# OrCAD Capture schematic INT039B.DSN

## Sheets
1 PAGE3 - CONFIG: size B; title: TUSB522PEVM INT039 Rev B: CONFIG; rev: B; note: 6590969
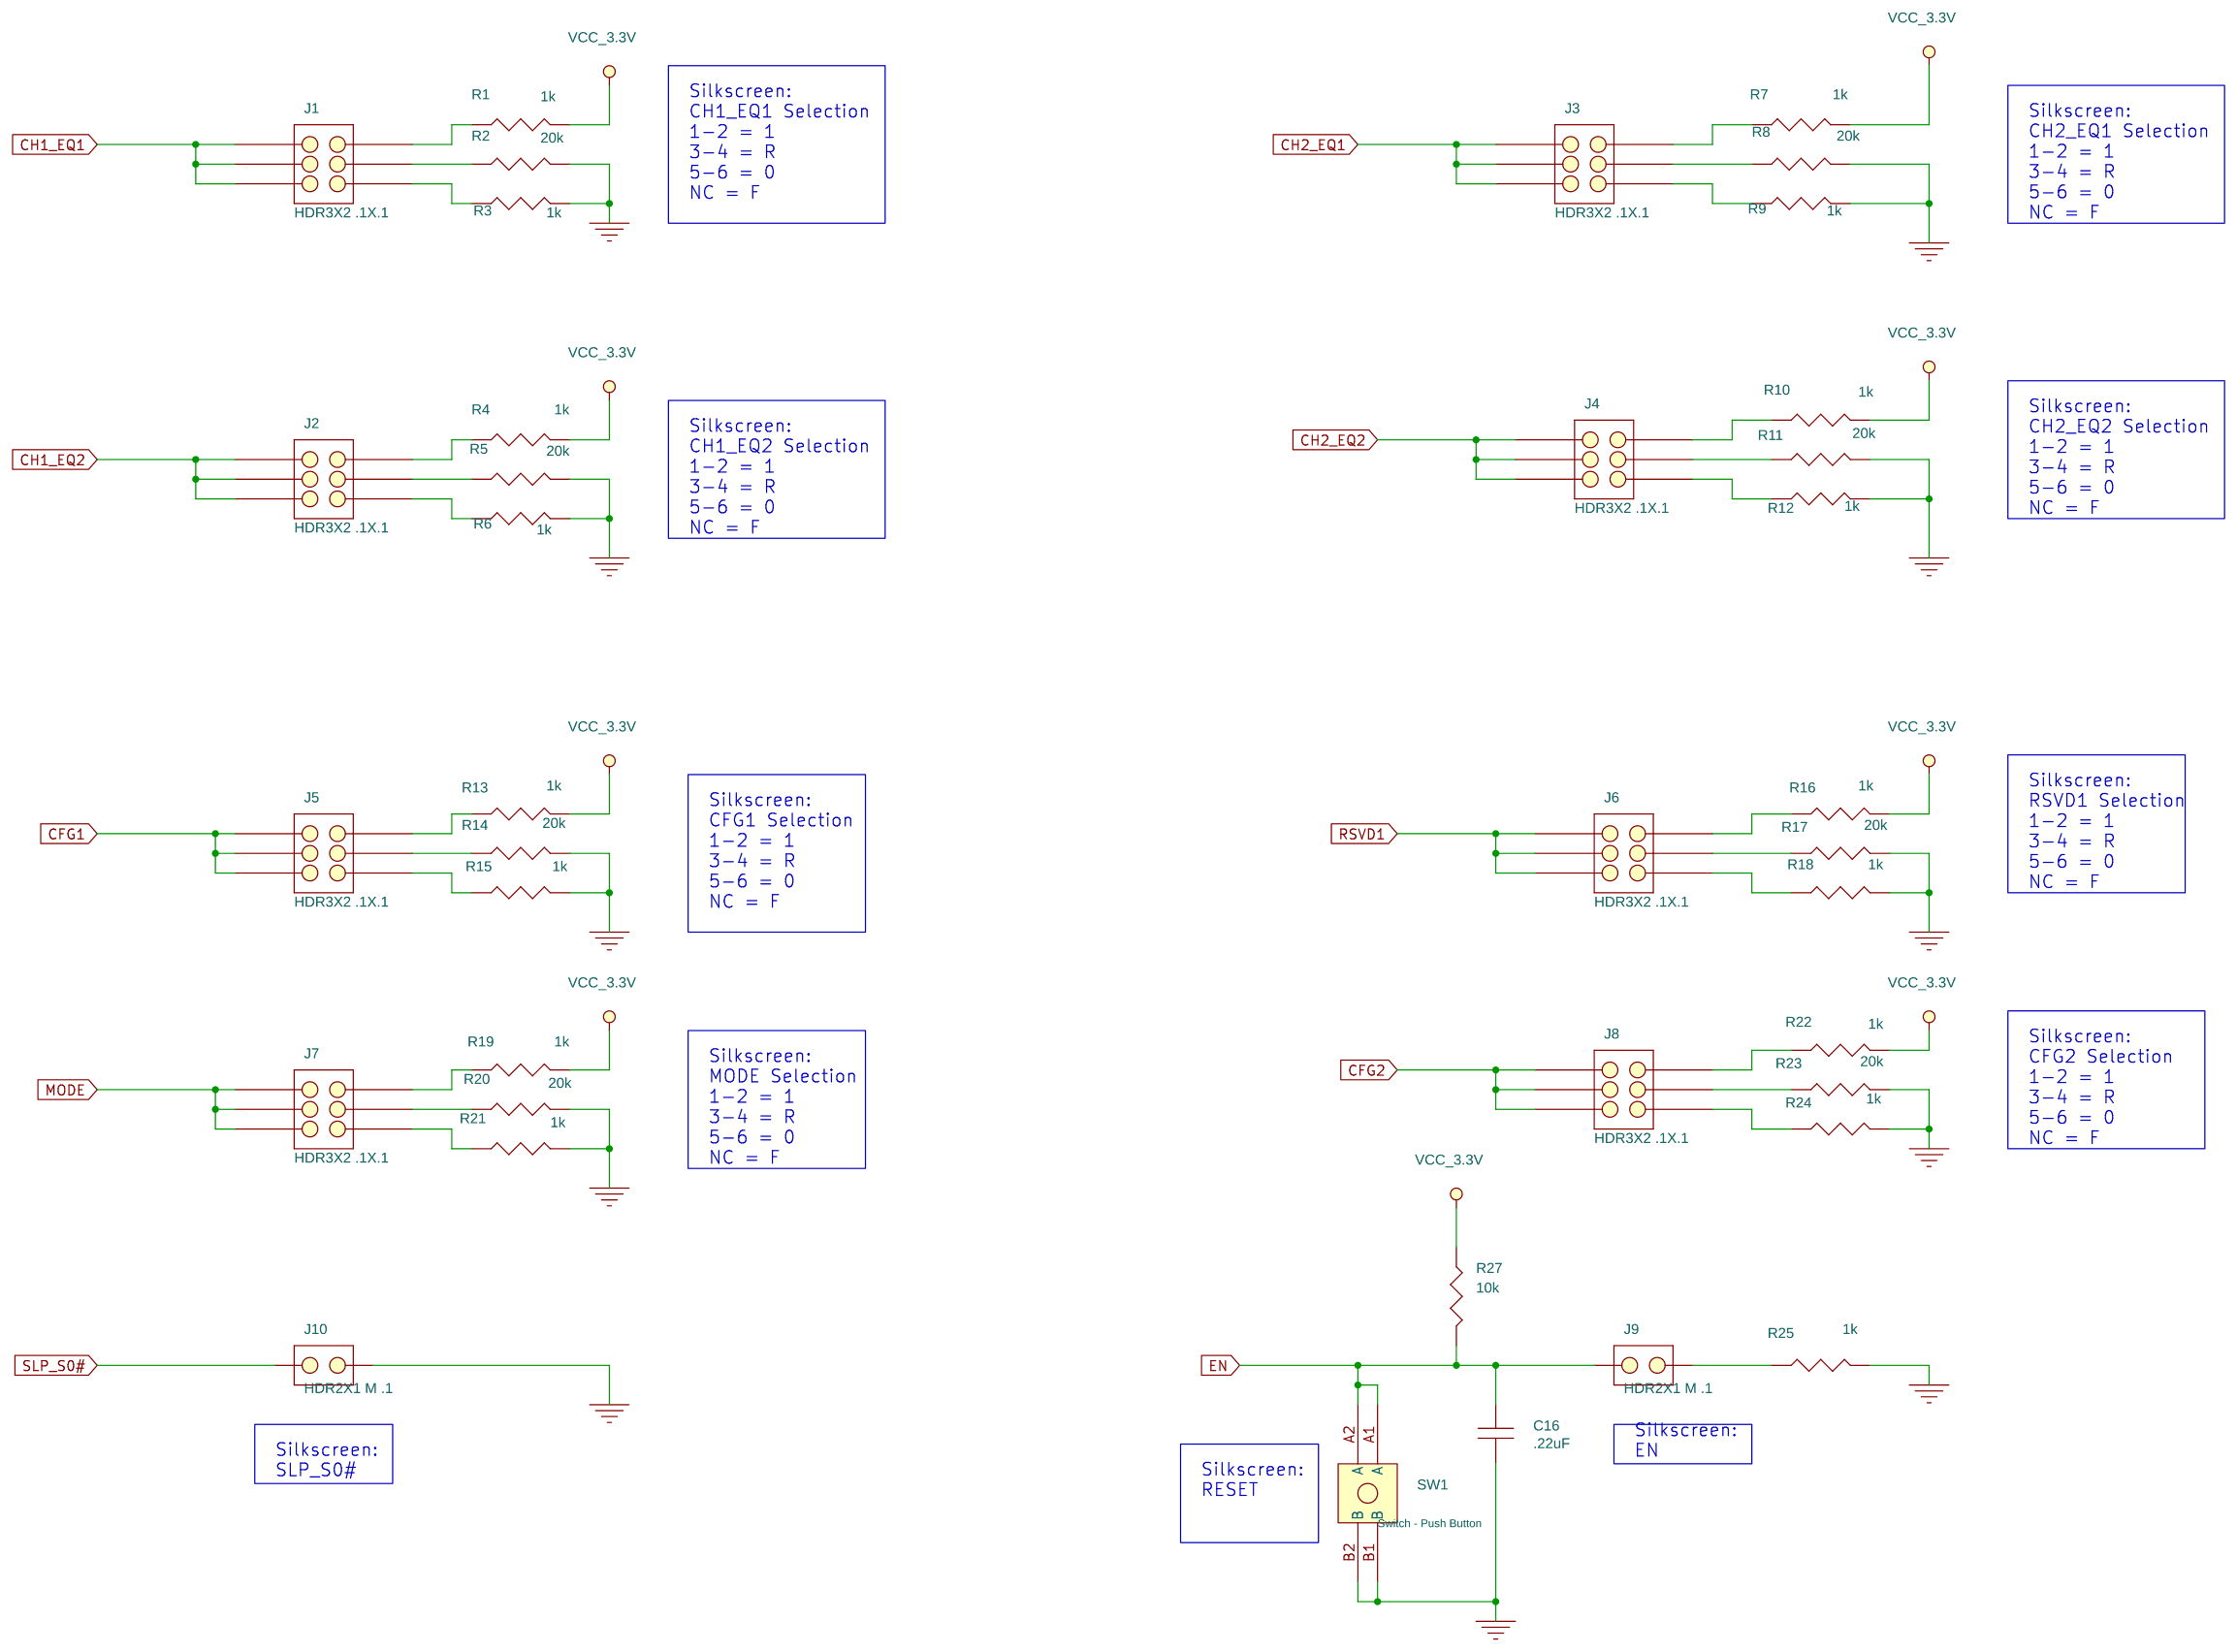
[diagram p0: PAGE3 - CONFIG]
2 PAGE1 - Block: title: TUSB522PEVM INT039 Rev B: Block
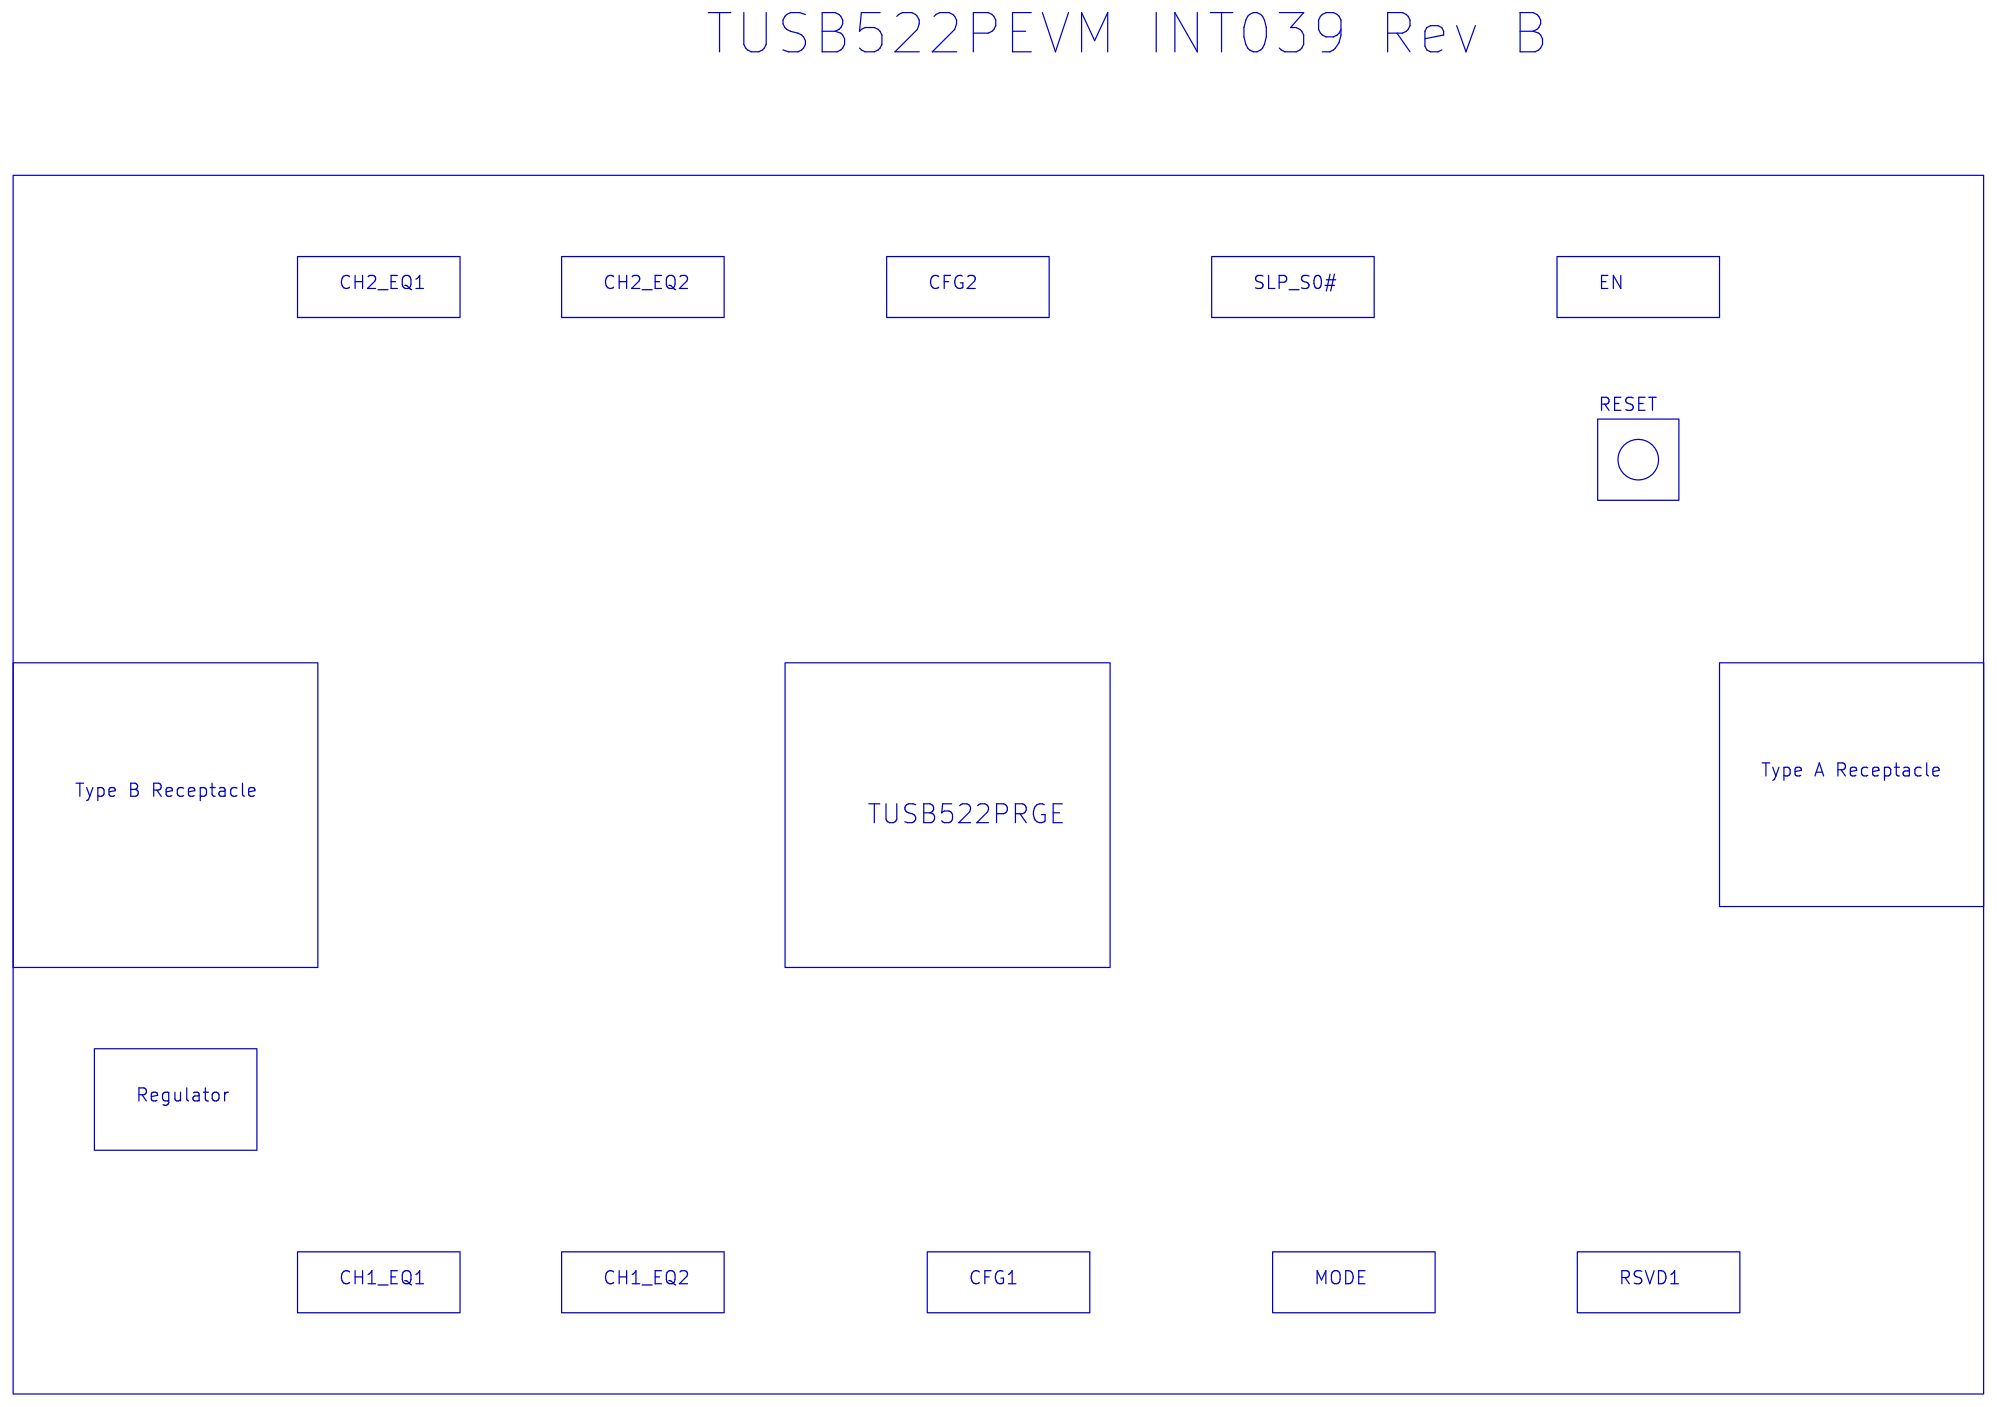
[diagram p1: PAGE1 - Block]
3 PAGE2 - HighSpeed/Power: size B; title: TUSB522PEVM INT039 Rev B: High-Speed/Power
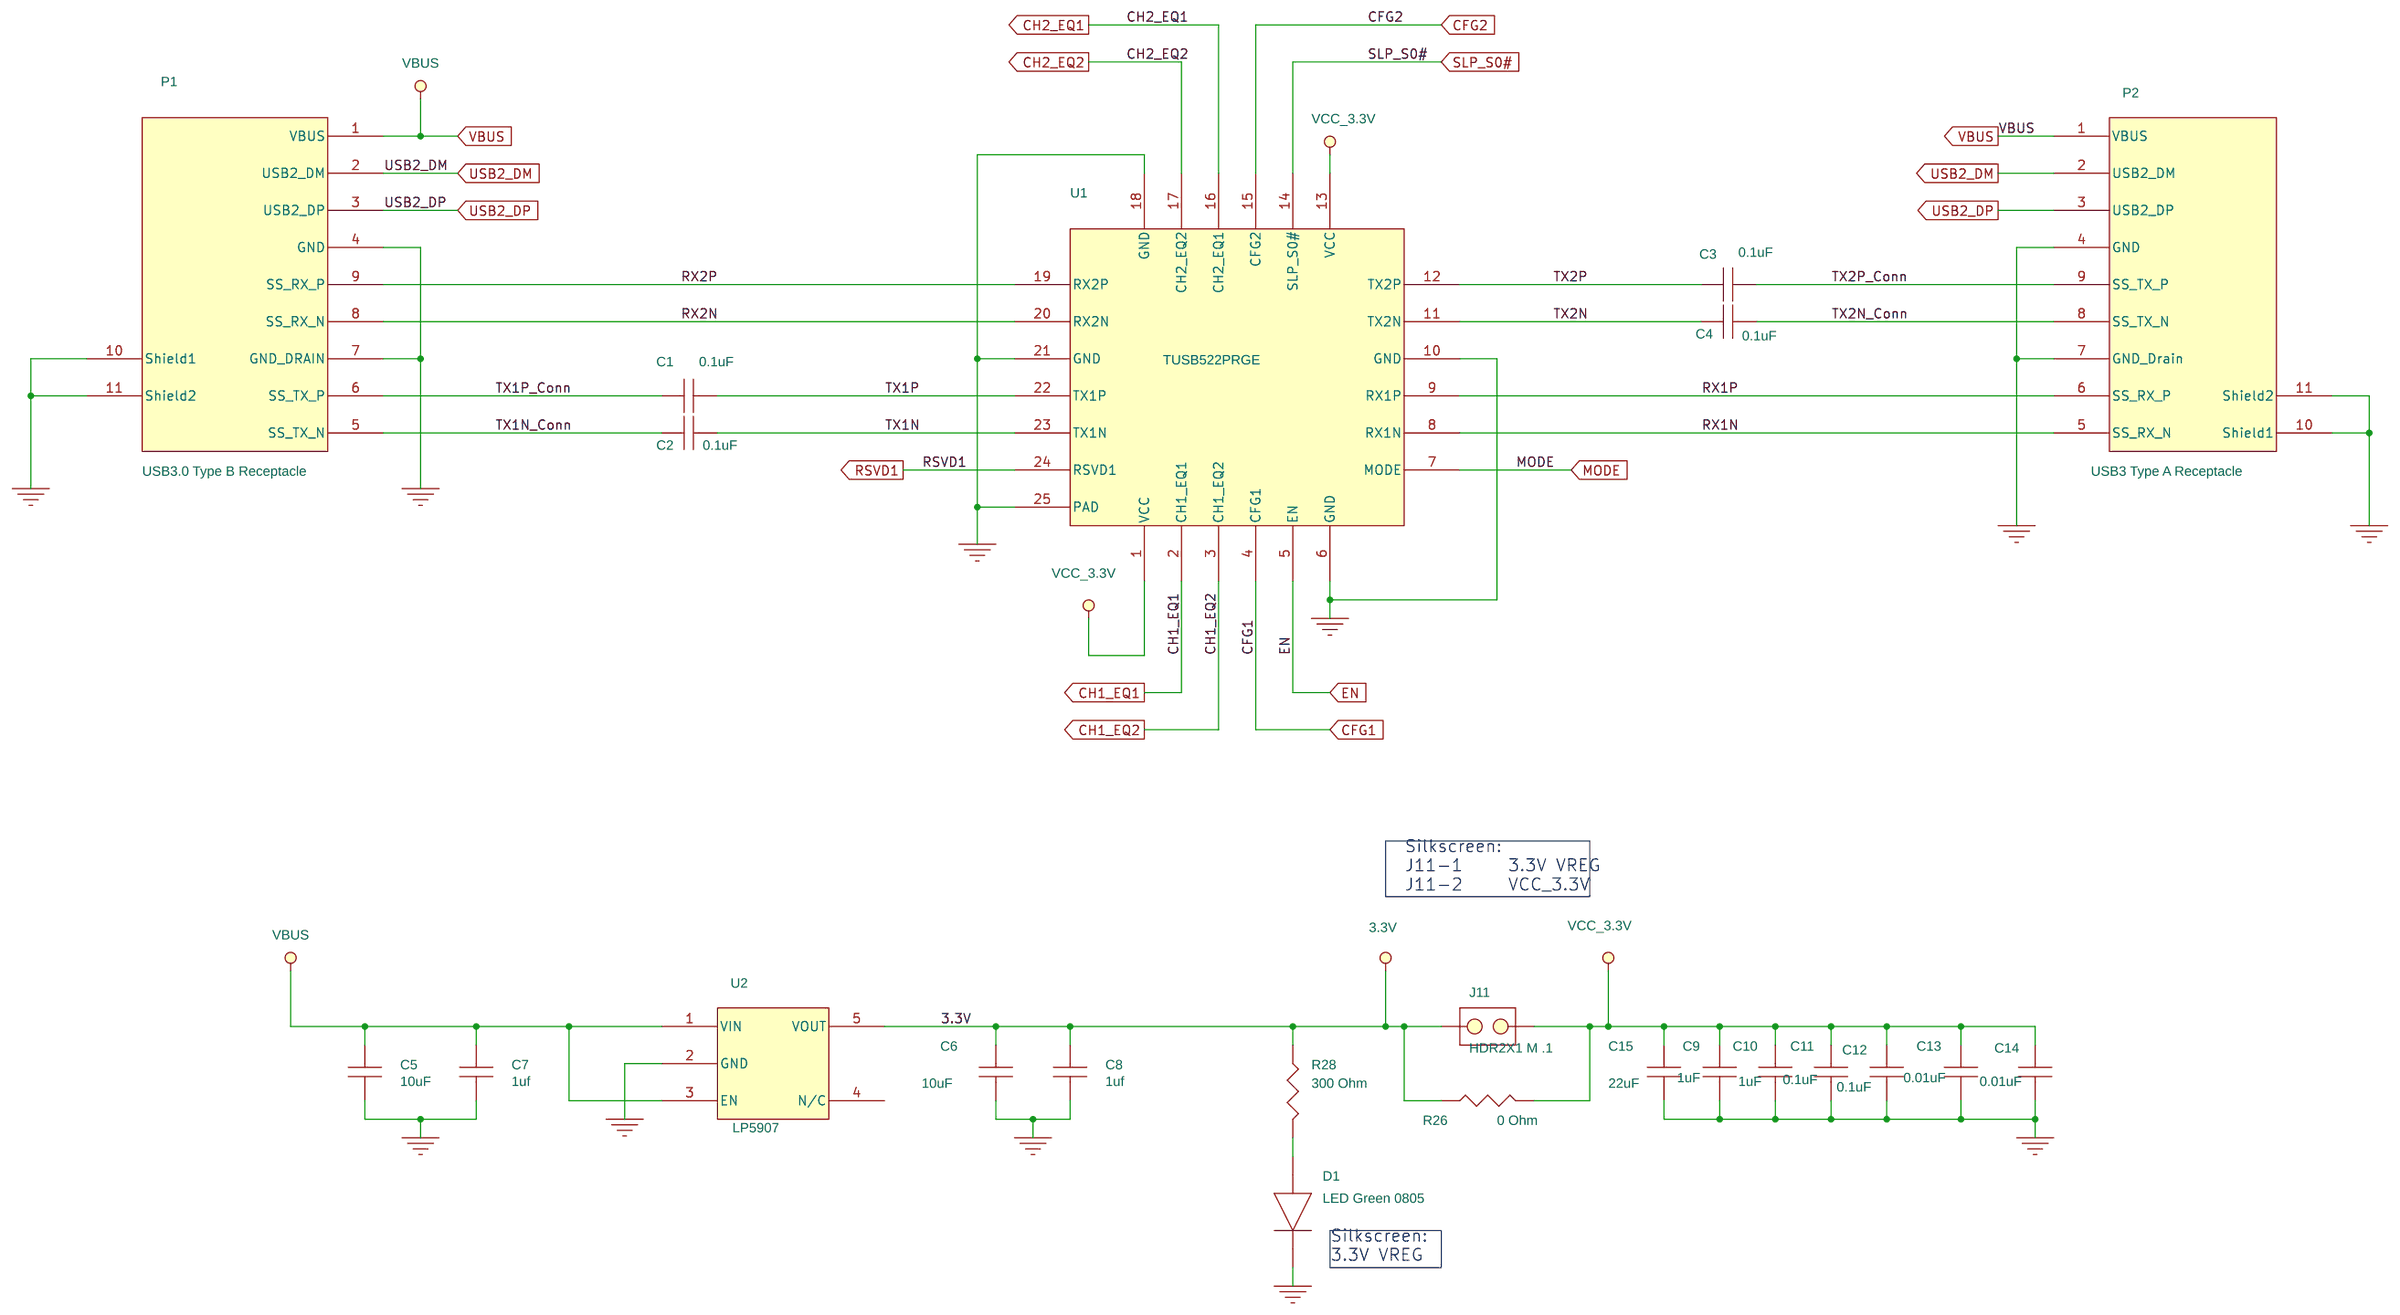
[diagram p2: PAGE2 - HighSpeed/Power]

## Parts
sheet PAGE2 - HighSpeed/Power
C1  0.1uF  [cc0201]
C2  0.1uF  [cc0201]
C3  0.1uF  [cc0201]
C4  0.1uF  [cc0201]
C5  10uF  [cc0805]
C6  10uF  [cc0805]
C7  1uf  [cc0603]
C8  1uf  [cc0603]
C9  1uF  [cc0201]
C10  1uF  [cc0201]
C11  0.1uF  [cc0201]
C12  0.1uF  [cc0201]
C13  0.01uF  [cc0201]
C14  0.01uF  [cc0201]
C15  22uF  [cc0805]
D1  LED Green 0805
J11  HDR2X1 M .1
P1  USB3.0 Type B Receptacle
P2  USB3 Type A Receptacle
R26  0 Ohm  [r0805]
R28  300 Ohm  [r0402]
U1  TUSB522PRGE  [QFN]
U2  LP5907  [DBV_R-PDSO-G5]
sheet PAGE3 - CONFIG
C16  .22uF  [cc0402]
J1  HDR3X2 .1X.1
J2  HDR3X2 .1X.1
J3  HDR3X2 .1X.1
J4  HDR3X2 .1X.1
J5  HDR3X2 .1X.1
J6  HDR3X2 .1X.1
J7  HDR3X2 .1X.1
J8  HDR3X2 .1X.1
J9  HDR2X1 M .1
J10  HDR2X1 M .1
R1  1k  [r0402]
R2  20k  [r0402]
R3  1k  [r0402]
R4  1k  [r0402]
R5  20k  [r0402]
R6  1k  [r0402]
R7  1k  [r0402]
R8  20k  [r0402]
R9  1k  [r0402]
R10  1k  [r0402]
R11  20k  [r0402]
R12  1k  [r0402]
R13  1k  [r0402]
R14  20k  [r0402]
R15  1k  [r0402]
R16  1k  [r0402]
R17  20k  [r0402]
R18  1k  [r0402]
R19  1k  [r0402]
R20  20k  [r0402]
R21  1k  [r0402]
R22  1k  [r0402]
R23  20k  [r0402]
R24  1k  [r0402]
R25  1k  [r0402]
R27  10k  [r0402]
SW1  Switch - Push Button

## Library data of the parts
C1-C4 C9-C14 = cc0201
C5 C6 C15 = cc0805
C7 C8 = cc0603_1.0uf_25V
D1 = LED_Green_0805
J9-J11 = HDR2X1_M_.1
P1 = USB_3.0_Type_B_Receptacle
P2 = USB_3.0_Type_A_Receptacle
R26 = r0805
R1-R25 R27 R28 = r0402
U1 = TUSB1002RGE
U2 = LP5907
C16 = cc0402
J1-J8 = HDR3X2_M_.1X.1
SW1 = Switch_-_Push_Button

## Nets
3.3V: C6.1 C8.1 J11.1 R26.1 R28.1 U2.5(VOUT)
GND: C5.2 C6.2 C7.2 C8.2 C9.2 C10.2 C11.2 C12.2 C13.2 C14.2 C15.2 C16.2 D1.CATHODE J10.2 P1.4(GND) P1.7(GND_DRAIN) P1.10(Shield1) P1.11(Shield2) P2.4(GND) P2.7(GND_Drain) P2.10(Shield1) P2.11(Shield2) R2.2 R3.2 R5.2 R6.2 R8.2 R9.2 R11.2 R12.2 R14.2 R15.2 R17.2 R18.2 R20.2 R21.2 R23.2 R24.2 R25.2 SW1.B1(B) SW1.B2(B) U1.6(GND) U1.10(GND) U1.18(GND) U1.21(GND) U1.25(PAD) U2.2(GND)
VBUS: C5.1 C7.1 P1.1(VBUS) P2.1(VBUS) U2.1(VIN) U2.3(EN)
VCC_3.3V: C9.1 C10.1 C11.1 C12.1 C13.1 C14.1 C15.1 J11.2 R1.2 R4.2 R7.2 R10.2 R13.2 R16.2 R19.2 R22.2 R26.2 R27.1 U1.1(VCC) U1.13(VCC)
CFG1: J5.1 J5.3 J5.5 U1.4(CFG1)
CFG2: J8.1 J8.3 J8.5 U1.15(CFG2)
CH1_EQ1: J1.1 J1.3 J1.5 U1.2(CH1_EQ1)
CH1_EQ2: J2.1 J2.3 J2.5 U1.3(CH1_EQ2)
CH2_EQ1: J3.1 J3.3 J3.5 U1.16(CH2_EQ1)
CH2_EQ2: J4.1 J4.3 J4.5 U1.17(CH2_EQ2)
EN: C16.1 J9.1 R27.2 SW1.A1(A) SW1.A2(A) U1.5(EN)
MODE: J7.1 J7.3 J7.5 U1.7(MODE)
RSVD1: J6.1 J6.3 J6.5 U1.24(RSVD1)
RX1N: P2.5(SS_RX_N) U1.8(RX1N)
RX1P: P2.6(SS_RX_P) U1.9(RX1P)
RX2N: P1.8(SS_RX_N) U1.20(RX2N)
RX2P: P1.9(SS_RX_P) U1.19(RX2P)
SLP_S0#: J10.1 U1.14(SLP_S0#)
TX1N: C2.2 U1.23(TX1N)
TX1N_Conn: C2.1 P1.5(SS_TX_N)
TX1P: C1.2 U1.22(TX1P)
TX1P_Conn: C1.1 P1.6(SS_TX_P)
TX2N: C4.1 U1.11(TX2N)
TX2N_Conn: C4.2 P2.8(SS_TX_N)
TX2P: C3.1 U1.12(TX2P)
TX2P_Conn: C3.2 P2.9(SS_TX_P)
USB2_DM: P1.2(USB2_DM) P2.2(USB2_DM)
USB2_DP: P1.3(USB2_DP) P2.3(USB2_DP)
N04057: J1.2 R1.1
N04069: J1.4 R2.1
N04073: J1.6 R3.1
N04156: J2.2 R4.1
N04168: J2.4 R5.1
N04172: J2.6 R6.1
N04339: J3.2 R7.1
N04351: J3.4 R8.1
N04355: J3.6 R9.1
N04442: J4.2 R10.1
N04460: J4.4 R11.1
N04464: J4.6 R12.1
N04816: J5.2 R13.1
N04828: J5.4 R14.1
N04832: J5.6 R15.1
N05035: J7.2 R19.1
N05047: J7.4 R20.1
N05051: J7.6 R21.1
N05588: J6.2 R16.1
N05600: J6.4 R17.1
N05604: J6.6 R18.1
N05749: J8.2 R22.1
N05761: J8.4 R23.1
N05765: J8.6 R24.1
N05896: J9.2 R25.1
N16532433: D1.ANNODE R28.2

Not connected (* = marked no-connect by the designer): U2 4(N/C)

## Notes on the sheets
sheet 1
- Silkscreen:
  CH1_EQ1 Selection
  1-2 = 1
  3-4 = R
  5-6 = 0
  NC = F
- Silkscreen:
  CH2_EQ1 Selection
  1-2 = 1
  3-4 = R
  5-6 = 0
  NC = F
- Silkscreen:
  CH2_EQ2 Selection
  1-2 = 1
  3-4 = R
  5-6 = 0
  NC = F
- Silkscreen:
  CH1_EQ2 Selection
  1-2 = 1
  3-4 = R
  5-6 = 0
  NC = F
- Silkscreen:
  RSVD1 Selection
  1-2 = 1
  3-4 = R
  5-6 = 0
  NC = F
- Silkscreen:
  CFG1 Selection
  1-2 = 1
  3-4 = R
  5-6 = 0
  NC = F
- Silkscreen:
  CFG2 Selection
  1-2 = 1
  3-4 = R
  5-6 = 0
  NC = F
- Silkscreen:
  MODE Selection
  1-2 = 1
  3-4 = R
  5-6 = 0
  NC = F
- Silkscreen:
  EN
- Silkscreen:
  SLP_S0#
- Silkscreen:
  RESET
sheet 2
- TUSB522PEVM INT039 Rev B
- CH2_EQ1
- CH2_EQ2
- CFG2
- SLP_S0#
- EN
- RESET
- Type A Receptacle
- Type B Receptacle
- TUSB522PRGE
- Regulator
- CH1_EQ1
- CH1_EQ2
- CFG1
- MODE
- RSVD1
sheet 3
- Silkscreen:
  J11-1     3.3V VREG
  J11-2     VCC_3.3V
- Silkscreen:
  3.3V VREG
